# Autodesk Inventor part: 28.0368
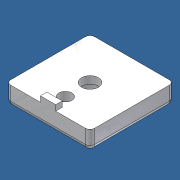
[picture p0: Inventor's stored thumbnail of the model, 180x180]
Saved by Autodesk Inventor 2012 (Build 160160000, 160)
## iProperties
Created: 2011-09
Part Number: 28.0368
Document SubType Name: Modeling
Designer: Administrator
Density: 2.71 g/cm^3
Mass: 49.7338 g
Surface Area: 60.868 cm^2
Volume: 18.3519 cm^3
Material: Aluminum-6061
Description: MINI ADJ BEARING SUPPORT 45X45
Vendor: S
Author: Administrator
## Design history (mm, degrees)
feature "Base1"
body "Solid1"
